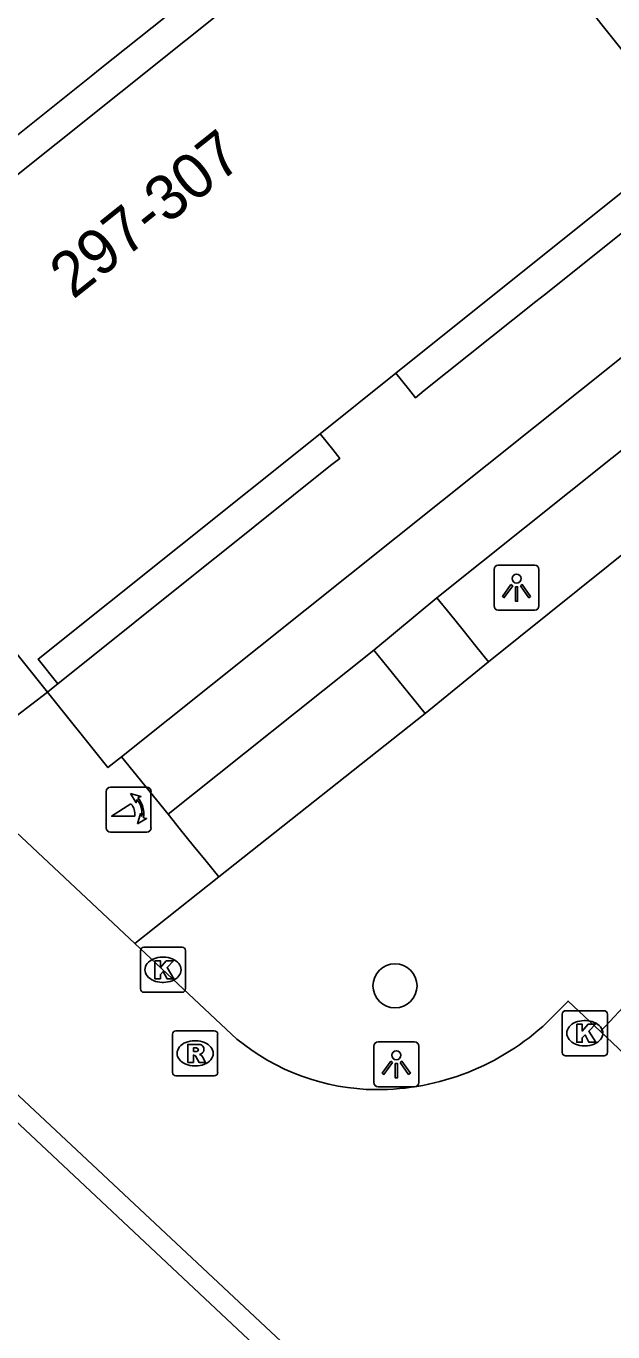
# Model space of a CAD drawing. Extents: x 159040 to 160094, y 381214 to 382518.
# Drawn here: x 159515.87 to 159528.9, y 381635.07 to 381664.06 of the extents above; entities that cross this region are included whole.
import ezdxf

# ---------------------------------------------------------------- set-up
doc = ezdxf.new("R2010")
doc.units = 0
for name, color, linetype in [('IMGEO_Boom', 7, 'Continuous'), ('IMGEO_Haag', 7, 'Continuous'), ('IMGEO_Kolk', 7, 'Continuous'), ('IMGEO_Lichtpunt', 7, 'Continuous'), ('IMGEO_Pand', 7, 'Continuous'), ('IMGEO_Pand_nummerreeks', 7, 'Continuous'), ('IMGEO_Pand_overbouw', 7, 'Continuous'), ('IMGEO_Poller', 7, 'Continuous'), ('IMGEO_Rijbaan_lokaal_open', 7, 'Continuous'), ('IMGEO_Rioolput', 7, 'Continuous'), ('IMGEO_Voetpad_gesloten', 7, 'Continuous'), ('IMGEO_Voetpad_open', 7, 'Continuous')]:
    doc.layers.add(name, color=color, linetype=linetype)

msp = doc.modelspace()

# ---------------------------------------------------------------- linework, layer by layer
at = {"layer": 'IMGEO_Boom'}
msp.add_circle((159524.058, 381642.756), 0.489, dxfattribs=at)
at = {"layer": 'IMGEO_Haag'}
for points in [[(159538.785, 381660.093), (159526.133, 381649.947)], [(159524.729, 381648.803), (159520.146, 381645.173)], [(159528.622, 381641.741), (159532.928, 381646.356), (159543.875, 381635.985)]]:
    msp.add_lwpolyline(points, dxfattribs=at)
at = {"layer": 'IMGEO_Kolk'}
for p, q in [((159518.406, 381642.686), (159518.406, 381643.538)), ((159518.481, 381643.612), (159519.333, 381643.612)), ((159519.407, 381643.538), (159519.407, 381642.686)), ((159518.894, 381643.392), (159518.919, 381643.392)), ((159519.333, 381642.612), (159518.481, 381642.612)), ((159518.917, 381642.832), (159518.892, 381642.832)), ((159527.772, 381641.277), (159527.772, 381642.129)), ((159527.847, 381642.203), (159528.699, 381642.203)), ((159528.773, 381642.129), (159528.773, 381641.277)), ((159528.26, 381641.983), (159528.285, 381641.983)), ((159528.283, 381641.423), (159528.258, 381641.423)), ((159528.699, 381641.203), (159527.847, 381641.203))]:
    msp.add_line(p, q, dxfattribs=at)
for points in [[(159518.406, 381642.686), (159518.406, 381643.538)], [(159518.481, 381643.612), (159519.333, 381643.612)], [(159519.407, 381643.538), (159519.407, 381642.686)], [(159518.727, 381643.312), (159518.85, 381643.312), (159518.85, 381643.161), (159518.98, 381643.312), (159519.144, 381643.312), (159518.998, 381643.161), (159519.151, 381642.912), (159518.999, 381642.912), (159518.914, 381643.076), (159518.85, 381643.009), (159518.85, 381642.912), (159518.727, 381642.912), (159518.727, 381643.312)], [(159519.333, 381642.612), (159518.481, 381642.612)], [(159527.772, 381641.277), (159527.772, 381642.129)], [(159527.847, 381642.203), (159528.699, 381642.203)], [(159528.773, 381642.129), (159528.773, 381641.277)], [(159528.093, 381641.903), (159528.216, 381641.903), (159528.216, 381641.752), (159528.346, 381641.903), (159528.51, 381641.903), (159528.364, 381641.752), (159528.517, 381641.503), (159528.365, 381641.503), (159528.28, 381641.667), (159528.216, 381641.6), (159528.216, 381641.503), (159528.093, 381641.503), (159528.093, 381641.903)], [(159528.699, 381641.203), (159527.847, 381641.203)]]:
    msp.add_lwpolyline(points, dxfattribs=at)
for centre, start, end in [((159518.483, 381643.536), 91.552, 178.448), ((159518.483, 381643.536), 91.552, 178.448), ((159519.331, 381643.536), 1.552, 88.448), ((159519.331, 381643.536), 1.552, 88.448), ((159518.483, 381642.688), 181.552, 268.448), ((159518.483, 381642.688), 181.552, 268.448), ((159519.331, 381642.688), 271.552, 358.448), ((159519.331, 381642.688), 271.552, 358.448), ((159527.849, 381642.127), 91.552, 178.448), ((159527.849, 381642.127), 91.552, 178.448), ((159528.697, 381642.127), 1.552, 88.448), ((159528.697, 381642.127), 1.552, 88.448), ((159527.849, 381641.279), 181.552, 268.448), ((159527.849, 381641.279), 181.552, 268.448), ((159528.697, 381641.279), 271.552, 358.448), ((159528.697, 381641.279), 271.552, 358.448)]:
    msp.add_arc(centre, 0.0765, start, end, dxfattribs=at)
for centre, major_axis, ratio, start_param, end_param in [((159518.893, 381643.112), (-0.387, 0.002), 0.722429, 4.712389, 7.853982), ((159518.918, 381643.112), (-0.39, 0.002), 0.717154, 1.570796, 4.712389), ((159528.259, 381641.703), (-0.387, 0.002), 0.722429, 4.712389, 7.853982), ((159528.284, 381641.703), (-0.39, 0.002), 0.717154, 1.570796, 4.712389)]:
    msp.add_ellipse(centre, major_axis=major_axis, ratio=ratio, start_param=start_param, end_param=end_param, dxfattribs=at)
at = {"layer": 'IMGEO_Lichtpunt'}
for p, q in [((159526.258, 381652), (159526.258, 381651.193)), ((159526.258, 381652), (159526.258, 381651.193)), ((159527.16, 381652.095), (159526.352, 381652.095)), ((159527.16, 381652.095), (159526.352, 381652.095)), ((159527.254, 381651.193), (159527.254, 381652)), ((159527.254, 381651.193), (159527.254, 381652)), ((159526.352, 381651.099), (159527.16, 381651.099)), ((159526.352, 381651.099), (159527.16, 381651.099)), ((159523.589, 381641.416), (159523.589, 381640.609)), ((159523.589, 381641.416), (159523.589, 381640.609)), ((159524.491, 381641.511), (159523.683, 381641.511)), ((159524.491, 381641.511), (159523.683, 381641.511)), ((159524.585, 381640.609), (159524.585, 381641.416)), ((159524.585, 381640.609), (159524.585, 381641.416)), ((159523.683, 381640.515), (159524.491, 381640.515)), ((159523.683, 381640.515), (159524.491, 381640.515))]:
    msp.add_line(p, q, dxfattribs=at)
for points in [[(159526.632, 381651.664), (159526.671, 381651.636), (159526.483, 381651.374), (159526.445, 381651.401), (159526.632, 381651.664)], [(159526.734, 381651.616), (159526.781, 381651.616), (159526.781, 381651.294), (159526.734, 381651.294), (159526.734, 381651.616)], [(159526.844, 381651.636), (159526.882, 381651.663), (159527.069, 381651.401), (159527.03, 381651.373), (159526.844, 381651.636)], [(159523.963, 381641.08), (159524.002, 381641.052), (159523.814, 381640.79), (159523.776, 381640.817), (159523.963, 381641.08)], [(159524.065, 381641.032), (159524.112, 381641.032), (159524.112, 381640.71), (159524.065, 381640.71), (159524.065, 381641.032)], [(159524.175, 381641.052), (159524.213, 381641.079), (159524.4, 381640.817), (159524.361, 381640.789), (159524.175, 381641.052)]]:
    msp.add_lwpolyline(points, dxfattribs=at)
for centre in [(159526.757, 381651.798), (159524.088, 381641.214)]:
    msp.add_circle(centre, 0.0994, dxfattribs=at)
for centre, start, end in [((159526.352, 381652), 90, 180), ((159526.352, 381652), 90, 180), ((159527.16, 381652), 0, 90), ((159527.16, 381652), 0, 90), ((159526.352, 381651.193), 180, 270), ((159526.352, 381651.193), 180, 270), ((159527.16, 381651.193), 270, 0), ((159527.16, 381651.193), 270, 360), ((159523.683, 381641.416), 90, 180), ((159523.683, 381641.416), 90, 180), ((159524.491, 381641.416), 0, 90), ((159524.491, 381641.416), 0, 90), ((159523.683, 381640.609), 180, 270), ((159523.683, 381640.609), 180, 270), ((159524.491, 381640.609), 270, 0), ((159524.491, 381640.609), 270, 360)]:
    msp.add_arc(centre, 0.0946, start, end, dxfattribs=at)
at = {"layer": 'IMGEO_Pand'}
for points in [[(159510.034, 381657.157), (159510.259, 381657.341), (159510.714, 381656.799), (159525.223, 381668.397)], [(159525.223, 381668.397), (159530.643, 381661.602)], [(159530.643, 381661.602), (159530.47, 381661.464), (159530.909, 381660.92), (159531.511, 381660.175), (159531.304, 381660.003), (159530.703, 381660.756), (159530.263, 381661.309), (159524.075, 381656.36), (159522.394, 381655.014), (159516.137, 381650.009), (159516.574, 381649.462), (159516.469, 381649.378), (159516.34, 381649.275)], [(159510.034, 381657.157), (159516.34, 381649.275)], [(159520.926, 381634.794), (159515.6, 381639.787)]]:
    msp.add_lwpolyline(points, dxfattribs=at)
at = {"layer": 'IMGEO_Pand_overbouw'}
for points in [[(159525.223, 381668.397), (159524.798, 381668.93), (159524.677, 381668.833), (159524.478, 381668.675), (159521.138, 381666.008), (159520.939, 381665.849), (159517.513, 381663.114), (159517.312, 381662.954), (159513.901, 381660.23), (159513.697, 381660.068), (159510.259, 381657.341), (159510.714, 381656.799)], [(159530.703, 381660.756), (159530.263, 381661.309), (159524.075, 381656.36), (159524.355, 381656.008), (159524.511, 381655.813), (159524.709, 381655.971), (159527.184, 381657.947), (159527.378, 381658.101)], [(159516.574, 381649.462), (159519.994, 381652.198), (159520.128, 381652.304), (159522.629, 381654.305), (159522.831, 381654.467), (159522.675, 381654.663), (159522.394, 381655.014), (159516.137, 381650.009)]]:
    msp.add_lwpolyline(points, close=True, dxfattribs=at)
at = {"layer": 'IMGEO_Poller'}
for p, q in [((159517.645, 381647.07), (159517.645, 381646.263)), ((159517.645, 381647.07), (159517.645, 381646.263)), ((159518.547, 381647.165), (159517.739, 381647.165)), ((159518.547, 381647.165), (159517.739, 381647.165)), ((159518.641, 381646.263), (159518.641, 381647.07)), ((159518.641, 381646.263), (159518.641, 381647.07)), ((159517.739, 381646.168), (159518.547, 381646.168)), ((159517.739, 381646.168), (159518.547, 381646.168))]:
    msp.add_line(p, q, dxfattribs=at)
for points in [[(159518.324, 381646.894), (159518.312, 381646.821), (159518.187, 381647.026)], [(159518.187, 381647.026), (159518.418, 381646.96), (159518.347, 381646.928)], [(159518.28, 381646.521), (159517.767, 381646.521), (159518.197, 381646.796)], [(159518.34, 381646.349), (159518.406, 381646.58), (159518.436, 381646.512)], [(159518.472, 381646.485), (159518.544, 381646.474), (159518.34, 381646.349)]]:
    msp.add_lwpolyline(points, dxfattribs=at)
for centre, radius, start, end in [((159517.739, 381647.07), 0.0946, 90, 180), ((159517.739, 381647.07), 0.0946, 90, 180), ((159517.966, 381646.581), 0.516, 349.3569, 42.2912), ((159518.547, 381647.07), 0.0946, 0, 90), ((159518.547, 381647.07), 0.0946, 0, 90), ((159517.952, 381646.571), 0.332, 351.3247, 42.4854), ((159517.966, 381646.581), 0.476, 351.7527, 41.1691), ((159517.739, 381646.263), 0.0946, 180, 270), ((159517.739, 381646.263), 0.0946, 180, 270), ((159518.547, 381646.263), 0.0946, 270, 0), ((159518.547, 381646.263), 0.0946, 270, 0)]:
    msp.add_arc(centre, radius, start, end, dxfattribs=at)
at = {"layer": 'IMGEO_Rijbaan_lokaal_open'}
for points in [[(159518.283, 381643.698), (159503.53, 381657.53)], [(159505.22, 381650.124), (159536.088, 381621.223), (159536.396, 381621.54), (159536.728, 381621.22)], [(159518.283, 381643.698), (159520.549, 381641.574)], [(159527.435, 381641.945), (159527.901, 381642.418), (159528.622, 381641.741)], [(159529.155, 381641.24), (159528.622, 381641.741)]]:
    msp.add_lwpolyline(points, dxfattribs=at)
for centre, radius, start, end in [((159523.652, 381645.984), 5.534, 269.7521, 313.1276), ((159523.673, 381645.353), 4.903, 230.4171, 269.4733)]:
    msp.add_arc(centre, radius, start, end, dxfattribs=at)
at = {"layer": 'IMGEO_Rioolput'}
for p, q in [((159519.195, 381641.756), (159520.047, 381641.756)), ((159519.12, 381640.83), (159519.12, 381641.682)), ((159519.608, 381641.536), (159519.633, 381641.536)), ((159520.121, 381641.682), (159520.121, 381640.83)), ((159519.631, 381640.976), (159519.606, 381640.976)), ((159520.047, 381640.756), (159519.195, 381640.756))]:
    msp.add_line(p, q, dxfattribs=at)
for points in [[(159519.195, 381641.756), (159520.047, 381641.756)], [(159519.12, 381640.83), (159519.12, 381641.682)], [(159519.709, 381641.454), (159519.457, 381641.456), (159519.457, 381641.056)], [(159520.121, 381641.682), (159520.121, 381640.83)], [(159519.457, 381641.056), (159519.581, 381641.056), (159519.581, 381641.218), (159519.592, 381641.218)], [(159519.635, 381641.375), (159519.581, 381641.375), (159519.581, 381641.294)], [(159519.581, 381641.294), (159519.633, 381641.294)], [(159519.639, 381641.189), (159519.71, 381641.056), (159519.85, 381641.056), (159519.785, 381641.182)], [(159520.047, 381640.756), (159519.195, 381640.756)]]:
    msp.add_lwpolyline(points, dxfattribs=at)
for centre, radius, start, end in [((159519.197, 381641.68), 0.0765, 91.552, 178.448), ((159519.197, 381641.68), 0.0765, 91.552, 178.448), ((159520.045, 381641.68), 0.0765, 1.552, 88.448), ((159520.045, 381641.68), 0.0765, 1.552, 88.448), ((159519.708, 381641.344), 0.109, 350.3612, 89.416), ((159519.591, 381641.165), 0.0533, 26.0293, 88.6989), ((159519.617, 381641.483), 0.19, 274.7715, 282.9687), ((159519.641, 381641.279), 0.0964, 77.0061, 93.1865), ((159519.655, 381641.336), 0.0378, 276.6634, 79.6772), ((159519.706, 381641.344), 0.112, 277.5842, 350.9817), ((159519.69, 381641.129), 0.108, 29.5134, 73.7905), ((159519.197, 381640.832), 0.0765, 181.552, 268.448), ((159519.197, 381640.832), 0.0765, 181.552, 268.448), ((159520.045, 381640.832), 0.0765, 271.552, 358.448), ((159520.045, 381640.832), 0.0765, 271.552, 358.448)]:
    msp.add_arc(centre, radius, start, end, dxfattribs=at)
for centre, major_axis, ratio, start_param, end_param in [((159519.607, 381641.256), (-0.387, 0.002), 0.722429, 4.712389, 7.853982), ((159519.632, 381641.256), (-0.39, 0.002), 0.717154, 1.570796, 4.712389)]:
    msp.add_ellipse(centre, major_axis=major_axis, ratio=ratio, start_param=start_param, end_param=end_param, dxfattribs=at)
at = {"layer": 'IMGEO_Voetpad_gesloten'}
for points in [[(159517.986, 381647.841), (159560.674, 381681.936), (159563.337, 381681.842), (159568.876, 381676.789), (159590.803, 381656.219)], [(159537.658, 381661.487), (159524.989, 381651.371)], [(159523.586, 381650.209), (159524.989, 381651.371)], [(159523.586, 381650.209), (159519.021, 381646.563)], [(159517.986, 381647.841), (159519.021, 381646.563)]]:
    msp.add_lwpolyline(points, dxfattribs=at)
at = {"layer": 'IMGEO_Voetpad_open'}
for points in [[(159516.34, 381649.275), (159515.647, 381648.74), (159509.353, 381656.604), (159510.034, 381657.157)], [(159524.989, 381651.371), (159525.287, 381651), (159525.569, 381650.649), (159525.851, 381650.298), (159526.133, 381649.947)], [(159524.729, 381648.803), (159524.445, 381649.153), (159524.161, 381649.502), (159523.877, 381649.851), (159523.586, 381650.209)], [(159526.133, 381649.947), (159524.729, 381648.803)], [(159516.34, 381649.275), (159517.686, 381647.602), (159517.986, 381647.841)], [(159519.021, 381646.563), (159519.297, 381646.222), (159519.58, 381645.872), (159519.863, 381645.522), (159520.146, 381645.173)], [(159520.146, 381645.173), (159518.283, 381643.698)]]:
    msp.add_lwpolyline(points, dxfattribs=at)

# ---------------------------------------------------------------- texts
at = {"layer": 'IMGEO_Pand_nummerreeks'}
msp.add_text('297-307', height=1, rotation=38.5791, dxfattribs=at).set_placement((159516.912, 381657.982))

doc.saveas('drawing.dxf')
